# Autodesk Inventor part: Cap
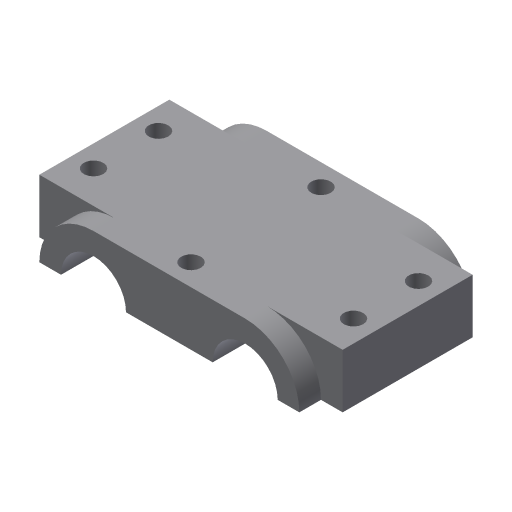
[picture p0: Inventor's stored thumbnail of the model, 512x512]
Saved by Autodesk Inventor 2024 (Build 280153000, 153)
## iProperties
Created: 2002-02
Part Number: Cap
Document SubType Name: Modeling
Designer: ***
Density: 1 g/cm^3
Material: Generic
Appearance: Default
Control State: 0
Master: False
Checked Out: False
Shininess: 77.0
Length Units: 11269
Angle Units: 11279
Time Units: 11290
Mass Units: 11283
Length Display Precision: 3
Angle Display Precision: 2
Density: 0.0
Volumn: 0.0
Area: 0.0
PropertySet Name: Model Information
Author: ***
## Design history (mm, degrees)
sketch "Sketch2"
  geometry: L1 (-17.5, 12.5)-(17.5, 12.5); L2 (30, 0)-(25, 0); L3 (10, 0)-(-10, 0); L4 (-25, 0)-(-30, 0); A1 r 12.5 centre (-17.5, 0) between (-17.5, 12.5) and (-30, 0); A2 r 12.5 centre (17.5, 0) between (30, 0) and (17.5, 12.5); A3 r 7.5 centre (17.5, 0) between (25, 0) and (10, 0); A4 r 7.5 centre (-17.5, 0) between (-10, 0) and (-25, 0)
  constraints: 8 end point, 8 point on circle, 4 centre point, 3 horizontal, 3 parallel, 2 coincident, 2 equal radius, 2 tangent
  dimensions: "d0" = 12.5 radius of A1; "d1" = 7.5 radius of A4; "d2" = 35 distance of A1.centre A2.centre; "d3" = 12.5 distance between parallel lines of L1 L3
extrude "Extrusion1" new body sketch "Sketch2" stored distance "d4" = 40; taper "d5" = 0 deg
workplane "Work Plane1"
sketch "Sketch3"
  geometry: L1 (-15, 12.5)-(15, 12.5); L2 (15, 12.5)-(15, 0); L3 (15, 0)-(-15, 0); L4 (-15, 0)-(-15, 12.5); L5 (-20, 0)-(20, 0) reference; L6 (-20, 12.5)-(20, 12.5) reference; L7 (20, 12.5)-(20, 0) reference
  constraints: 8 end point, 2 collinear, 2 parallel, 1 horizontal, 1 perpendicular
  dimensions: "d7" = 30 distance of L2.end L3.end; "d8" = 5 distance between parallel lines of L7 L2
extrude "Extrusion2" join sketch "Sketch3" stored distance "d9" = 40; taper "d10" = 0 deg
mirror "Mirror1"
sketch "Sketch4"
  geometry: L1 (-17.5, -35)-(0, -35) reference; L2 (-17.5, -35)-(-17.5, -5) reference; 1 further point
  dimensions: "d12" = 7.5 distance from line of L1 point (-12.5, -27.5); "d13" = 5 distance from line of L2 point (-12.5, -27.5)
hole "Hole1" sketch "Sketch4" diameter "d14" = 4.5; stored, may be unused: countersink angle "d18" = 82 deg, drill point angle "d20" = 118 deg; dims "d15" = 6, "d16" = 4, "d17" = 2, "d19" = 8
pattern_linear "Rectangular Pattern1" dims "d23" = 60, "d26" = 15
sketch "Sketch5"
  geometry: L1 (0, -40)-(35, -40) reference; L2 (-17.5, -35)-(-17.5, -5) reference; 1 further point
  dimensions: "d27" = 5 distance from line of L1 point (17.5, -35); "d28" = 35 distance from line of L2 point (17.5, -35)
hole "Hole2" sketch "Sketch5" diameter "d29" = 4.5; stored, may be unused: countersink angle "d33" = 82 deg, drill point angle "d35" = 118 deg; dims "d30" = 6, "d31" = 4, "d32" = 2, "d34" = 8
pattern_linear "Rectangular Pattern2" dims "d38" = 30
body "Solid1"
other parameters: "d11" = 35
